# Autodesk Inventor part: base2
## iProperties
Created: 2008-03
Part Number: base2
Document SubType Name: Modeling
Designer: t-ikumi
Density: 1 g/cm^3
Author: t-ikumi
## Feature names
1. 押し出し1 [Extrusion]
2. 押し出し2 [Extrusion]
